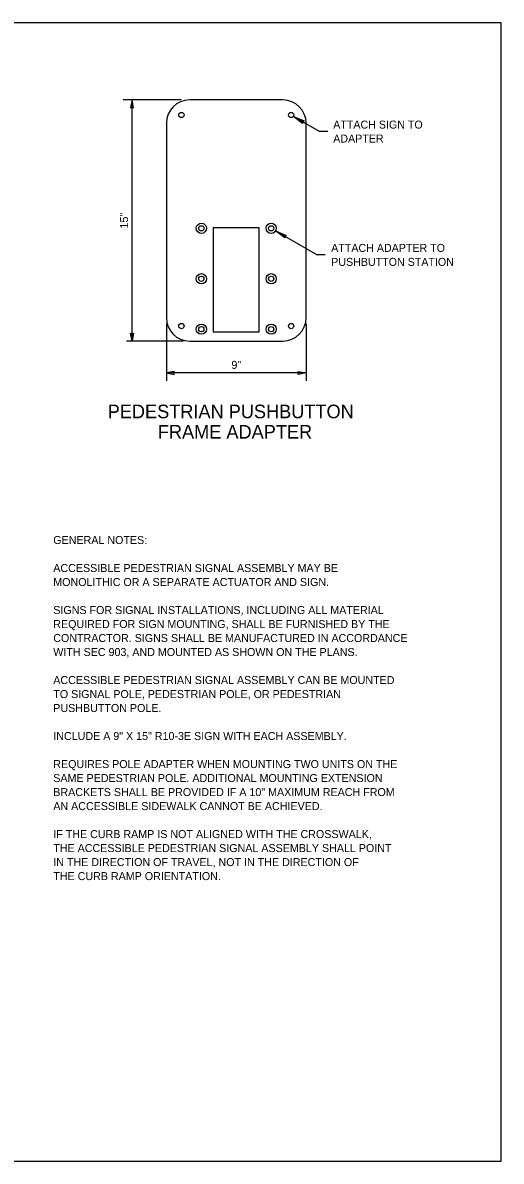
# Model space of a CAD drawing. Extents: x 2815109 to 2818234, y 992846 to 994883.
# Drawn here: x 2817378 to 2818234, y 992846 to 994883 of the extents above; entities that cross this region are included whole.
import ezdxf

# ---------------------------------------------------------------- set-up
doc = ezdxf.new("R2010")
doc.units = 0
for name, color, linetype in [('Common-Dimensions', 7, 'Continuous'), ('Common-Notes', 7, 'Continuous'), ('Draft_Named_Boundary', 7, 'Continuous'), ('Level 15', 7, 'Continuous'), ('Level 20', 7, 'Continuous'), ('Level 41', 7, 'Continuous')]:
    doc.layers.add(name, color=color, linetype=linetype)

msp = doc.modelspace()

# ---------------------------------------------------------------- linework, layer by layer
at = {"layer": 'Common-Dimensions'}
for p, q in [((2817862.4, 994716), (2817909.6, 994688.8)), ((2817924, 994688.8), (2817909.6, 994688.8)), ((2817830.6, 994511), (2817904.9, 994468.1)), ((2817919.3, 994468.1), (2817904.9, 994468.1))]:
    msp.add_line(p, q, dxfattribs=at)
for points in [[(2817862.4, 994716), (2817881.5, 994708.1), (2817879.4, 994706.2), (2817878.8, 994703.4)], [(2817830.6, 994511), (2817849.7, 994503), (2817847.5, 994501.2), (2817847, 994498.4)]]:
    msp.add_lwpolyline(points, close=True, dxfattribs=at)
at = {"layer": 'Draft_Named_Boundary'}
msp.add_lwpolyline([(2815109.5, 992846), (2818234.5, 992846), (2818234.5, 994883.5), (2815109.5, 994883.5)], close=True, dxfattribs=at)
at = {"layer": 'Level 15'}
for p, q in [((2817661.4, 994745.3), (2817557.8, 994745.3)), ((2817573.6, 994313.7), (2817573.6, 994745.3)), ((2817635, 994344.6), (2817635, 994242.4)), ((2817885.2, 994344.6), (2817885.2, 994242.4)), ((2817665.9, 994313.7), (2817563.7, 994313.7)), ((2817885.2, 994256.8), (2817635, 994256.8))]:
    msp.add_line(p, q, dxfattribs=at)
for points in [[(2817573.6, 994745.3), (2817570.9, 994731.2), (2817573.6, 994731.8), (2817576.4, 994731.2)], [(2817573.6, 994313.7), (2817570.9, 994327.9), (2817573.6, 994327.2), (2817576.4, 994327.9)], [(2817635, 994256.8), (2817649.1, 994254.1), (2817648.5, 994256.8), (2817649.1, 994259.6)], [(2817885.2, 994256.8), (2817871.1, 994254.1), (2817871.7, 994256.8), (2817871.1, 994259.6)]]:
    msp.add_lwpolyline(points, close=True, dxfattribs=at)
at = {"layer": 'Level 41'}
for p, q in [((2817843.5, 994745.3), (2817676.7, 994745.3)), ((2817635, 994703.6), (2817635, 994355.4)), ((2817885.2, 994355.4), (2817885.2, 994703.6)), ((2817676.7, 994313.7), (2817843.5, 994313.7))]:
    msp.add_line(p, q, dxfattribs=at)
msp.add_lwpolyline([(2817801.3, 994516.2), (2817718.9, 994516.2), (2817718.9, 994330.4), (2817801.3, 994330.4)], close=True, dxfattribs=at)
for centre, radius in [((2817661.9, 994718.4), 4.72), ((2817858.3, 994718.4), 4.72), ((2817697.6, 994515.6), 9.19), ((2817822.6, 994515.6), 9.19), ((2817697.6, 994515.6), 4.72), ((2817822.6, 994515.6), 4.72), ((2817697.6, 994425.3), 9.19), ((2817697.6, 994425.3), 4.72), ((2817822.6, 994425.3), 9.19), ((2817822.6, 994425.3), 4.72), ((2817661.9, 994340.7), 4.72), ((2817697.6, 994335.1), 9.19), ((2817822.6, 994335.1), 9.19), ((2817858.3, 994340.7), 4.72), ((2817697.6, 994335.1), 4.72), ((2817822.6, 994335.1), 4.72)]:
    msp.add_circle(centre, radius, dxfattribs=at)
for centre, start, end in [((2817676.7, 994703.6), 90, 180), ((2817843.5, 994703.6), 0, 90), ((2817676.7, 994355.4), 180, 270), ((2817843.5, 994355.4), 270, 0)]:
    msp.add_arc(centre, 41.7, start, end, dxfattribs=at)

# ---------------------------------------------------------------- texts
at = {"layer": 'Common-Dimensions'}
for s, height, p in [('ATTACH SIGN TO ', 14.28, (2817933.7, 994694.1)), ('ADAPTER ', 14.28, (2817933.7, 994669.1)), ('ATTACH ADAPTER TO ', 14.28, (2817930.1, 994473.4)), ('PUSHBUTTON STATION ', 14.28, (2817930.1, 994448.4)), ('GENERAL NOTES:', 14.321, (2817432.5, 993950.6)), ('ACCESSIBLE PEDESTRIAN SIGNAL ASSEMBLY MAY BE ', 14.321, (2817432.5, 993900.5)), ('MONOLITHIC OR A SEPARATE ACTUATOR AND SIGN.', 14.321, (2817432.5, 993875.4)), ('SIGNS FOR SIGNAL INSTALLATIONS, INCLUDING ALL MATERIAL', 14.321, (2817432.5, 993825.3)), ('REQUIRED FOR SIGN MOUNTING, SHALL BE FURNISHED BY THE ', 14.321, (2817432.5, 993800.2)), ('CONTRACTOR. SIGNS SHALL BE MANUFACTURED IN ACCORDANCE ', 14.321, (2817432.5, 993775.2)), ('WITH SEC 903, AND MOUNTED AS SHOWN ON THE PLANS.', 14.321, (2817432.5, 993750.1)), ('ACCESSIBLE PEDESTRIAN SIGNAL ASSEMBLY CAN BE MOUNTED', 14.321, (2817432.5, 993700)), ('TO SIGNAL POLE, PEDESTRIAN POLE, OR PEDESTRIAN ', 14.321, (2817432.5, 993674.9)), ('PUSHBUTTON POLE.', 14.321, (2817432.5, 993649.9)), ('INCLUDE A 9" X 15" R10-3E SIGN WITH EACH ASSEMBLY.', 14.321, (2817432.5, 993599.8)), ('REQUIRES POLE ADAPTER WHEN MOUNTING TWO UNITS ON THE', 14.321, (2817432.5, 993549.6)), ('SAME PEDESTRIAN POLE. ADDITIONAL MOUNTING EXTENSION ', 14.321, (2817432.5, 993524.6)), ('BRACKETS SHALL BE PROVIDED IF A 10" MAXIMUM REACH FROM ', 14.321, (2817432.5, 993499.5)), ('AN ACCESSIBLE SIDEWALK CANNOT BE ACHIEVED.', 14.321, (2817432.5, 993474.4)), ('IF THE CURB RAMP IS NOT ALIGNED WITH THE CROSSWALK, ', 14.321, (2817432.5, 993424.3)), ('THE ACCESSIBLE PEDESTRIAN SIGNAL ASSEMBLY SHALL POINT', 14.321, (2817432.5, 993399.3)), ('IN THE DIRECTION OF TRAVEL, NOT IN THE DIRECTION OF ', 14.321, (2817432.5, 993374.2)), ('THE CURB RAMP ORIENTATION.', 14.321, (2817432.5, 993349.1))]:
    msp.add_text(s, height=height, dxfattribs=at).set_placement(p)
at = {"layer": 'Common-Notes'}
for s, p in [('PEDESTRIAN PUSHBUTTON', (2817529.9, 994175.7)), ('FRAME ADAPTER', (2817619.7, 994139.3))]:
    msp.add_text(s, height=24.3, dxfattribs=at).set_placement(p)
at = {"layer": 'Level 20'}
msp.add_text('15"', height=14.4, rotation=90, dxfattribs=at).set_placement((2817566.4, 994515.2))
msp.add_text('9"', height=14.4, dxfattribs=at).set_placement((2817751.4, 994264))

doc.saveas('drawing.dxf')
